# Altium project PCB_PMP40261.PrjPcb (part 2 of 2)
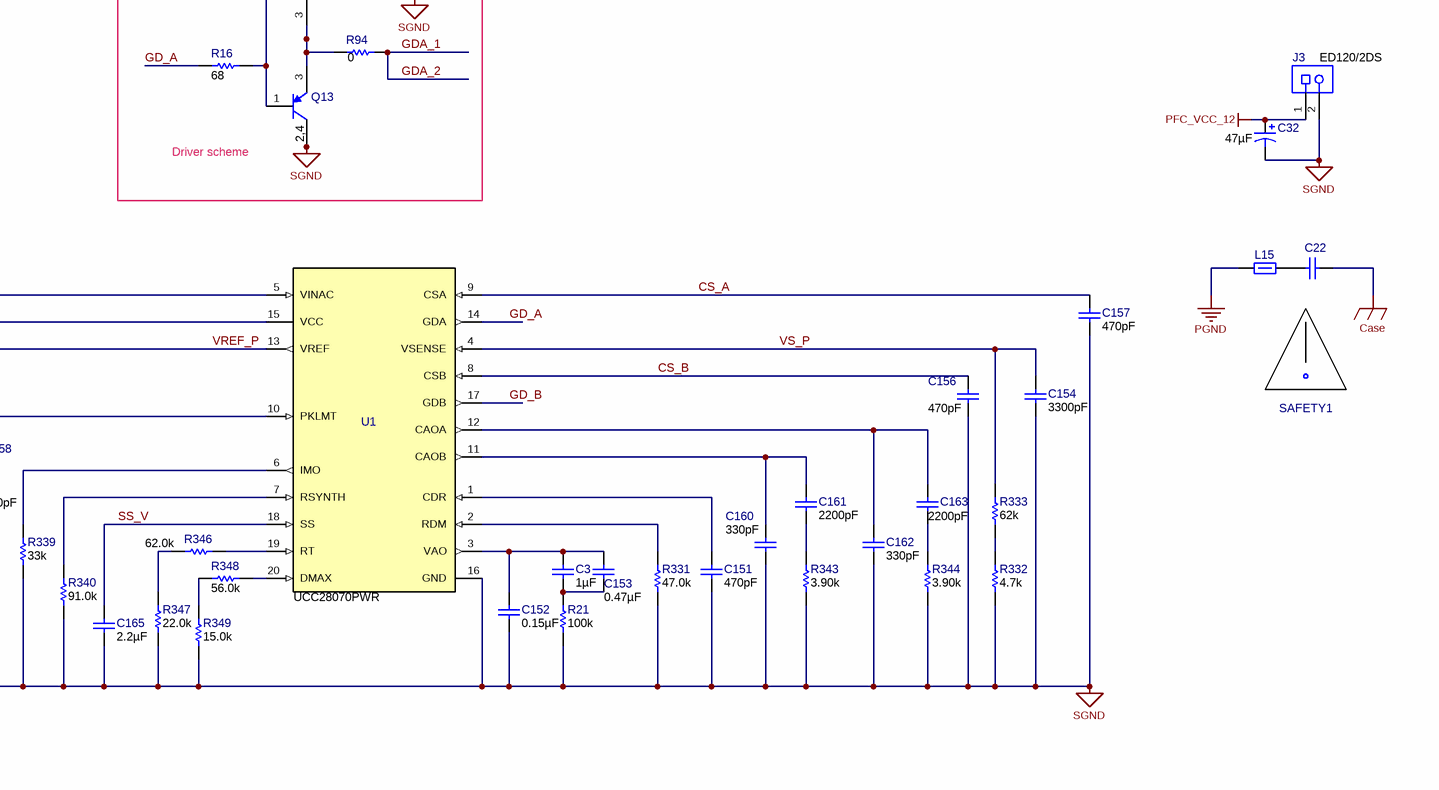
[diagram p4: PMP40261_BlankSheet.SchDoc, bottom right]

## Sheet PMP40261_BlankSheet.SchDoc (continued)

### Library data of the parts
C3 = UMK107AB7105KA-T: CAP, CERM, 1 µF, 50 V,+/- 10%, X7R, 0603; Manufacturer: Taiyo Yuden; Polarized: N; CompType: Capacitor; Value: 1uF; U/M: EA; Cap_F: 0.000001; Tolerance_%: 10; VDC_V: 50; Value2: 50V; TaMin_C: -55; TaMax_C: 125; SizeArea_mm2: 1.28; SizeAreaWB_mm2: 4.68; SizeX_mm: 1.6; SizeY_mm: 0.8; SizeZ_mm: 1; AEC Category: Q200; Green_Lifecycle: Active; Green_REACh: Passed
C11-C14 C41 = CMP-0078590-1: CAP, Film, 0.47 µF, X2 275 VAC, +/- 10%, TH; Manufacturer: Kemet; Cap_F: 470nF; SizeAreaWB_mm2: 210; VAC_X: 275; SizeArea_mm2: 153; AEC Qualified: N; AEC Category: Q200; Value: 0.47uF; TaMax_C: 110°C; SizeZ_mm: 14.6; TaMin_C: -40°C; SizeY_mm: 8.5; CompType: Capacitor; SizeX_mm: 18; Cap_Case: 18x8.5x14.5
C15 C16 = CMP-0009600-2: CAP, CERM, 1000 pF, 250 V, +/- 20%, E, Disc, 8x12mm; Manufacturer: MuRata; TaMin_C: -25°C; Polarized: N; SizeAreaWB_mm2: 100; Value1: Unknown; U/M: EA; Value: 1000pF; TaMax_C: 85°C; SizeZ_mm: 12; SizeX_mm: 8; Value2: 250V; SizeArea_mm2: 64; CompType: Capacitor; Cap_F: 1nF; AEC Category: Q200
C17 C18 = CMP-0009610-2: CAP, CERM, 2200 pF, 250 V, +/- 20%, E, Radial D8x5mm; Manufacturer: MuRata; TaMin_C: -25°C; Polarized: N; SizeAreaWB_mm2: 70; Value1: Unknown; U/M: EA; Value: 2200pF; TaMax_C: 85°C; SizeZ_mm: 11; SizeX_mm: 8; SizeY_mm: 5; Value2: 250V; SizeArea_mm2: 40; CompType: Capacitor; Cap_F: 2.2nF; AEC Category: Q200
C22 = CMP-0078745-1: CAP, CERM, 220 pF, X1 250 VAC/Y1 300 VAC, +/- 10%, B, 8x7mm; Manufacturer: MuRata; Cap_F: 220pF; SizeAreaWB_mm2: 158.76; VAC_X: 250V; VAC_Y: 300V; SizeArea_mm2: 112.36; AEC Qualified: N; AEC Category: Q200; Value: 220pF; TaMax_C: 125°C; SizeZ_mm: 11; TaMin_C: -40°C; SizeY_mm: 10.6; U/M: EA; AC_Safety: X1Y1; CompType: Capacitor
C27-C30 = CMP-0009975-3: CAP, AL, 150 uF, 450 V, +/- 20%, TH; Manufacturer: Rubycon; TaMax_C: 105°C; Value1: Unknown; SizeX_mm: 18; TaMin_C: -40°C; CompType: Capacitor; SizeZ_mm: 47; AEC Qualified: N; Value: 150uF; SizeArea_mm2: 324; AEC Category: Q200; SizeAreaWB_mm2: 400; U/M: EA; Polarized: Y; Cap_Case: 18x45mm; Cap_F: 150µF; IRMS_A: 1A
C31 = ECWF6223JL: CAP, Film, 0.022 µF, 630 V,+/- 5%, TH; Manufacturer: Panasonic; Polarized: N; CompType: Capacitor; Value: 0.022uF; U/M: EA; Cap_F: 0.000000022; Tolerance_%: 5; VDC_V: 630; Value2: 630V; TaMin_C: -40; TaMax_C: 105; Cap_Case: 12.5x6.2x10.5mm; AEC Category: Q200
C32 = EEU-FC1V470: CAP, AL, 47 µF, 35 V, +/- 20%, AEC-Q200 Grade 2, TH; Manufacturer: Panasonic; Polarized: Y; CompType: Capacitor; Value: 47uF; U/M: EA; Cap_F: 0.000047; Tolerance_%: 20; VDC_V: 35; Value2: 35V; IRMS_A: 0.29; TaMin_C: -55; TaMax_C: 105; Cap_Case: 6.3x11.2mm; SizeAreaWB_mm2: 68.89; SizeArea_mm2: 39.69; SizeX_mm: 6.3; SizeZ_mm: 12.2; AEC Category: Q200; AEC Grade: 2
C40 C43 C165 C181 = C2012X7R1H225K125AC: CAP, CERM, 2.2 µF, 50 V,+/- 10%, X7R, 0805; Manufacturer: TDK; Polarized: N; CompType: Capacitor; Value: 2.2uF; U/M: EA; Cap_F: 0.0000022; Tolerance_%: 10; ESR_ohm: 0.00366; Value1: 0.00366 ohm; VDC_V: 50; Value2: 50V; IRMS_A: 3.41207; TaMin_C: -55; TaMax_C: 125; Cap_Case: 0805; SizeArea_mm2: 2.5; SizeAreaWB_mm2: 6.75; SizeX_mm: 2; SizeY_mm: 1.25; SizeZ_mm: 1.45; AEC Category: Q200; Green_Lifecycle: Active; Green_REACh: Passed
C42 C44 C146 C159 C164 C178-C180 = GRM188R71H104KA93D: CAP, CERM, 0.1 µF, 50 V,+/- 10%, X7R, 0603; Manufacturer: MuRata; Polarized: N; CompType: Capacitor; Value: 0.1uF; U/M: EA; Cap_F: 0.0000001; Tolerance_%: 10; VDC_V: 50; Value2: 50V; TaMin_C: -55; TaMax_C: 125; SizeArea_mm2: 1.28; SizeAreaWB_mm2: 4.68; SizeX_mm: 1.6; SizeY_mm: 0.8; SizeZ_mm: 1; AEC Category: Q200; Green_Lifecycle: Active; Green_REACh: Passed
C80-C85 = CMP-0078744-1: CAP, CERM, 100 pF, 1000 V,+/- 10%, R, AEC-Q200 Grade 1, 6x5mm; Manufacturer: TDK; Cap_F: 100pF; SizeAreaWB_mm2: 56; SizeArea_mm2: 30; AEC Qualified: Y; AEC Category: Q200; Value: 100pF; TaMax_C: 125°C; SizeZ_mm: 10; AEC Grade: 1; Polarized: N; TaMin_C: -40°C; VDC_V: 1kV; SizeY_mm: 5; Value2: 1000V; U/M: EA; CompType: Capacitor; SizeX_mm: 6; Cap_Case: 6x5x10mm
C151 = 06031C471KAT2A: CAP, CERM, 470 pF, 100 V,+/- 10%, X7R, 0603; Manufacturer: AVX; Polarized: N; CompType: Capacitor; Value: 470pF; U/M: EA; Cap_F: 0.00000000047; Tolerance_%: 10; ESR_ohm: 0.397; Value1: 0.397 ohm; VDC_V: 100; Value2: 100V; TaMin_C: -55; TaMax_C: 125; SizeArea_mm2: 1.28; SizeAreaWB_mm2: 4.68; SizeX_mm: 1.6; SizeY_mm: 0.8; SizeZ_mm: 1; AEC Category: Q200; Green_Lifecycle: Not Set; Green_REACh: Incomplete
C152 = C1608X7R1E154K080AA: CAP, CERM, 0.15 µF, 25 V,+/- 10%, X7R, 0603; Manufacturer: TDK; Polarized: N; CompType: Capacitor; Value: 0.15uF; U/M: EA; Cap_F: 0.00000015; Tolerance_%: 10; VDC_V: 25; Value2: 25V; TaMin_C: -55; TaMax_C: 125; SizeArea_mm2: 1.28; SizeAreaWB_mm2: 4.68; SizeX_mm: 1.6; SizeY_mm: 0.8; SizeZ_mm: 1; AEC Category: Q200; Green_Lifecycle: Active; Green_REACh: Passed
C153 = C1608X7R1H474K080AC: CAP, CERM, 0.47 µF, 50 V,+/- 10%, X7R, 0603; Manufacturer: TDK; Polarized: N; CompType: Capacitor; Value: 0.47uF; U/M: EA; Cap_F: 0.00000047; Tolerance_%: 10; ESR_ohm: 0.010974; Value1: 0.010974 ohm; VDC_V: 50; Value2: 50V; IRMS_A: 1.57483; TaMin_C: -55; TaMax_C: 125; SizeArea_mm2: 1.28; SizeAreaWB_mm2: 4.68; SizeX_mm: 1.6; SizeY_mm: 0.8; SizeZ_mm: 1; AEC Category: Q200; Green_Lifecycle: Active; Green_REACh: Passed
C154 C155 = 06031C332JAT2A: CAP, CERM, 3300 pF, 100 V,+/- 5%, X7R, 0603; Manufacturer: AVX; Polarized: N; CompType: Capacitor; Value: 3300pF; U/M: EA; Cap_F: 0.0000000033; Tolerance_%: 5; ESR_ohm: 0.159; Value1: 0.159 ohm; VDC_V: 100; Value2: 100V; TaMin_C: -55; TaMax_C: 125; SizeArea_mm2: 1.28; SizeAreaWB_mm2: 4.68; SizeX_mm: 1.6; SizeY_mm: 0.8; SizeZ_mm: 1; AEC Category: Q200; Green_Lifecycle: Active; Green_REACh: Passed
C156 C157 = 06031C471JAT2A: CAP, CERM, 470 pF, 100 V,+/- 5%, X7R, 0603; Manufacturer: AVX; Polarized: N; CompType: Capacitor; Value: 470pF; U/M: EA; Cap_F: 0.00000000047; Tolerance_%: 5; ESR_ohm: 0.397; Value1: 0.397 ohm; VDC_V: 100; Value2: 100V; TaMin_C: -55; TaMax_C: 125; SizeArea_mm2: 1.28; SizeAreaWB_mm2: 4.68; SizeX_mm: 1.6; SizeY_mm: 0.8; SizeZ_mm: 1; AEC Category: Q200; Green_Lifecycle: Active; Green_REACh: Passed
C158 = 0603ZC101KAT2A: CAP, CERM, 100 pF, 10 V,+/- 10%, X7R, 0603; Manufacturer: AVX; Polarized: N; CompType: Capacitor; Value: 100pF; U/M: EA; Cap_F: 0.0000000001; Tolerance_%: 10; Value2: 10V; TaMin_C: -55; TaMax_C: 125; SizeArea_mm2: 1.28; SizeAreaWB_mm2: 4.68; SizeX_mm: 1.6; SizeY_mm: 0.8; SizeZ_mm: 1; AEC Category: Q200
C160 C162 = C0603C331K5RACTU: CAP, CERM, 330 pF, 50 V,+/- 10%, X7R, 0603; Manufacturer: Kemet; Polarized: N; CompType: Capacitor; Value: 330pF; U/M: EA; Cap_F: 0.00000000033; Tolerance_%: 10; VDC_V: 50; Value2: 50V; TaMin_C: -55; TaMax_C: 125; SizeArea_mm2: 1.28; SizeAreaWB_mm2: 4.68; SizeX_mm: 1.6; SizeY_mm: 0.8; SizeZ_mm: 1; AEC Category: Q200; Green_Lifecycle: Active; Green_REACh: Passed
C161 C163 = C0603C222K5RACTU: CAP, CERM, 2200 pF, 50 V,+/- 10%, X7R, 0603; Manufacturer: Kemet; Polarized: N; CompType: Capacitor; Value: 2200pF; U/M: EA; Cap_F: 0.0000000022; Tolerance_%: 10; VDC_V: 50; Value2: 50V; TaMin_C: -55; TaMax_C: 125; SizeArea_mm2: 1.28; SizeAreaWB_mm2: 4.68; SizeX_mm: 1.6; SizeY_mm: 0.8; SizeZ_mm: 1; AEC Category: Q200; Green_Lifecycle: Active; Green_REACh: Passed
D1 D2 = GBJ2510-F: Diode, Switching-Bridge, 1000 V, 25 A, TH; Manufacturer: Diodes Inc.; U/M: EA; Vf_V: 1.05; Value: 1000V; Value1: 25A; Value2: 1.05V; Io_A: 25; Vr_V: 1000; TJmax_C: 150; RJC_CperW: 0.6; SizeAreaWB_mm2: 211.2; SizeArea_mm2: 138; SizeX_mm: 30; SizeY_mm: 4.6; SizeZ_mm: 24; AEC Category: Q101; AEC Qualified: N
D3 D4 = CMP-0078592-2: Diode, Schottky, 650 V, 20 A, TH; Manufacturer: Rohm; Value2: 1.55V; Value1: 20A; SizeX_mm: 10.045; SizeY_mm: 4.445; SizeZ_mm: 20; AEC Qualified: N; Value: 650V; SizeArea_mm2: 44.650025; AEC Category: Q101; SizeAreaWB_mm2: 77.630025; Tjmax_C: 175°C; RJC_CperW: 3.2
D10-D13 = US1J-13-F: Diode, Ultrafast, 600 V, 1 A, SMA; Manufacturer: Diodes Inc.; U/M: EA; Vf_V: 1.7; Value: 600V; Value1: 1A; Value2: 1.7V; Io_A: 1; Vr_V: 600; TJmax_C: 150; SizeAreaWB_mm2: 37.3428; SizeArea_mm2: 16.3228; SizeX_mm: 5.59; SizeY_mm: 2.92; SizeZ_mm: 2.87; AEC Category: Q101; Green_Lifecycle: Active; Green_REACh: Passed
D14 D15 = RF071M2S: Diode, Ultrafast, 200 V, 1 A, SOD-123; Manufacturer: Rohm; U/M: EA; Vf_V: 0.85; Value: 200V; Value1: 1A; Value2: 0.85V; Io_A: 1; Vr_V: 200; TJmax_C: 150; SizeAreaWB_mm2: 13.095; SizeArea_mm2: 6.545; SizeX_mm: 3.85; SizeY_mm: 1.7; SizeZ_mm: 1.35; AEC Category: Q101; Green_Lifecycle: Not Set; Green_REACh: Incomplete
D16 D82 = 1N4148W-7-F: Diode, Ultrafast, 100 V, 0.3 A, SOD-123; Manufacturer: Diodes Inc.; U/M: EA; Vf_V: 1.25; Value: 100V; Value1: 0.15A; Value2: 1.25V; Io_A: 0.15; Vr_V: 100; TJmax_C: 150; SizeAreaWB_mm2: 13.095; SizeArea_mm2: 6.545; SizeX_mm: 3.85; SizeY_mm: 1.7; SizeZ_mm: 1.35; AEC Category: Q101; Green_Lifecycle: Active; Green_REACh: Passed
D20 D23 D25 D27 D65 = 1N4148W-7-F: Diode, Ultrafast, 100 V, 0.3A, SOD-123; Manufacturer: Diodes Inc.; U/M: EA; Vf_V: 1.25; Value: 100V; Value1: 0.15A; Value2: 1.25V; Io_A: 0.15; Vr_V: 100; TJmax_C: 150; SizeAreaWB_mm2: 13.095; SizeArea_mm2: 6.545; SizeX_mm: 3.85; SizeY_mm: 1.7; SizeZ_mm: 1.35; AEC Category: Q101; Green_Lifecycle: Active; Green_REACh: Passed
D21 D24 D26 D28 = BZT52B16-HE3-08: Diode, Zener, 16 V, 410 mW, AEC-Q101, SOD-123; Manufacturer: Vishay-Semiconductor; SymbolCreator: a0412235; U/M: EA; Power_W: 0.41; Vz_V: 16; Value1: 0.41W; RJA_CperW: 300; SizeAreaWB_mm2: 13.095; SizeArea_mm2: 6.545; SizeX_mm: 3.85; SizeY_mm: 1.7; SizeZ_mm: 1.35; AEC Category: Q101; AEC Qualified: Y
D50 = BAS16LT1G: Diode, Switching, 100 V, 0.2 A, SOT-23; Manufacturer: ON Semiconductor; U/M: EA; Vf_V: 1.25; Value: 100V; Value1: 0.2A; Value2: 1.25V; Io_A: 0.2; Vr_V: 100; TJmax_C: 150; SizeAreaWB_mm2: 14; SizeArea_mm2: 7.5; SizeX_mm: 2.5; SizeY_mm: 3; SizeZ_mm: 1.1; AEC Category: Q101; AEC Qualified: N; Green_Lifecycle: Active; Green_REACh: Passed
D51 = BAT54-7-F: Diode, Schottky, 30 V, 0.2 A, SOT-23; Manufacturer: Diodes Inc.; U/M: EA; Vf_V: 0.65; Value: 30V; Value1: 0.2A; Value2: 0.65V; Io_A: 0.2; Vr_V: 30; TJmax_C: 125; SizeAreaWB_mm2: 14; SizeArea_mm2: 7.5; SizeX_mm: 2.5; SizeY_mm: 3; SizeZ_mm: 1.1; AEC Category: Q101; Green_Lifecycle: Active; Green_REACh: Passed
F1 = CMP-0077109-1: Fuse, 12 A, 250 VAC, TH; Manufacturer: Shenzhen Deer Electronics Co., Ltd; Irating_A: 12A; SizeAreaWB_mm2: 216.6; VAC_V: 250V; SizeZ_mm: 5.8; SizeY_mm: 5.6; SizeX_mm: 26.5; SizeArea_mm2: 148.4
H2 = CMP-0078706-3: Heat Sink, 201x110x15mm; Manufacturer: Suzhou Baojieer
J1 = 1-1318301-2: Polarized Header, 7.92 mm, 2x1, Tin, TH; Manufacturer: TE Connectivity; SymbolCreator: a0412235; CompType: Connector; Pitch_mm: 7.92; Gender: Male; Shrouded: N; Row_Count: 1; Current_A: 7.5; Voltage_V: 250; Cert_UL: Y; Green_Lifecycle: Not Set; Green_REACh: Incomplete
J2 = ED120/3DS: Terminal Block, 5.08 mm, 3x1, Brass, TH; Manufacturer: On-Shore Technology; SymbolCreator: a0412235; Pitch_mm: 5.08; Gender: Female; Shrouded: N; Row_Count: 1; Current_A: 15; Voltage_V: 300; Cert_CULUS: Y; Green_Lifecycle: Not Set; Green_REACh: Incomplete
J3 = ED120/2DS: Terminal Block, 5.08 mm, 2x1, Brass, TH; Manufacturer: On-Shore Technology; SymbolCreator: a0412235; Pitch_mm: 5.08; Gender: Female; Shrouded: N; Row_Count: 1; Current_A: 15; Voltage_V: 300; Cert_CULUS: Y; Green_Lifecycle: Not Set; Green_REACh: Incomplete
K1 = CMP-0077099-1: Relay, SPDT (1 Form C), 16 A, 12 V, TH; Manufacturer: Omron Electronic Components; Coil Type: Non Latching; SizeAreaWB_mm2: 446.6; Contact Rating_A: 16A; Turn Off Voltage (Min)_VDC: 1.2V; SizeArea_mm2: 360.0; Turn On Voltage (Max)_VDC: 8.4V; Time Release (s): 5ms; SizeZ_mm: 15.7; Time Operate (s): 15ms; Coil Current_A: 33.3mA; Coil Voltage_VDC: 12V; SizeY_mm: 28.8; Coil Power_W: 400mW; SizeX_mm: 12.5; Coil Resistance_ohm: 360
L1-L4 = CMP-0078768-1: Inductor, Toroid, 130 µH, 0.018 ohm, TH; Manufacturer: Coilcraft; SizeAreaWB_mm2: 3136; SizeArea_mm2: 2916; AEC Qualified: N; AEC Category: Q200; Value: 130uH; SizeZ_mm: 28; SizeY_mm: 54; Value2: A; DCR_ohm: 0.018
L5 L6 = CMP-0077117-6: Coupled inductor, 2.5mH, TH; Manufacturer: Wurth Elektronik; SizeX_mm: 36.0; SizeZ_mm: 23.5; AEC Qualified: N; SizeArea_mm2: 1296.0; AEC Category: Q200; SizeAreaWB_mm2: 1444; Lp: 2500.0; Ns1toNp: 1.0
L7 = CMP-0078634-1: Coupled inductor, 4mH,  ohm, TH; Manufacturer: Wurth Elektronik; SizeAreaWB_mm2: 1444; SizeArea_mm2: 1296; AEC Qualified: N; AEC Category: Q200; SizeZ_mm: 23.5; SizeY_mm: 36
L8 = CMP-0077117-6: Shorted; PartNumber: 750343684; Manufacturer: Wurth Elektronik; SizeX_mm: 36.0; CompType: Coupled Inductor; SizeZ_mm: 23.5; AEC Qualified: N; SizeArea_mm2: 1296.0; AEC Category: Q200; SizeAreaWB_mm2: 1444; Lp: 2500.0; Ns1toNp: 1.0
L9-L12 = 28L0138-10R-10: Ferrite Bead, 75 ohm @ 100 MHz, 5 A, D3.51xL4.45mm; Manufacturer: Laird-Signal Integrity Products; Value: 75 ohm; Imax_A: 5; DCR_ohm: 0.01; Value1: 0.01 ohm; Value2: 5A; SizeAreaWB_mm2: 60.2243; SizeArea_mm2: 31.3443; SizeX_mm: 8.93; SizeY_mm: 3.51; SizeZ_mm: 3.76; ZTyp@100MHz_Ohm: 75; Green_Lifecycle: Not Set; Green_REACh: Incomplete
L15-L31 = 28L0138-10R-10: Ferrite Bead, 75 ohm @ 100 MHz, 5 A, D3.51xL4.45mm; Manufacturer: Laird-Signal Integrity Products; ValueDisplayed: 75 ohm; Value: 75 ohm; Imax_A: 5; DCR_ohm: 0.01; Value1: 0.01 ohm; Value2: 5A; SizeAreaWB_mm2: 60.2243; SizeArea_mm2: 31.3443; SizeX_mm: 8.93; SizeY_mm: 3.51; SizeZ_mm: 3.76; ZTyp@100MHz_Ohm: 75; Green_Lifecycle: Not Set; Green_REACh: Incomplete
L40 = CMP-0078767-1: Inductor, Toroid, 220 µH, 0.018 ohm, TH; Manufacturer: Coilcraft; SizeAreaWB_mm2: 1560.25; SizeArea_mm2: 1406.25; AEC Qualified: N; AEC Category: Q200; Value: 220uH; SizeZ_mm: 29; SizeY_mm: 37.5; Value2: A; DCR_ohm: 0.018
NT1-NT3 = Net-Tie: Single point connection between nets.; SymbolCreator: codlsc
Q1-Q4 = CMP-0078591-1: MOSFET, N-CH, 600 V, 35 A, TO-247; Manufacturer: Infineon Technologies; Alternate Manufacturer: None; ChType: N; QgTyp_nC: 68; SizeAreaWB_mm2: 600.8691; SizeArea_mm2: 501.9591; IdsMax_A: 35A; VdsMax_V: 600V; Vgs_V: 20V; AEC Category: Q101; Value: 600V; SizeZ_mm: 5.21; SizeY_mm: 31.54; Value2: 68 nC; U/M: EA; Value1: ? ohm; SizeX_mm: 15.915
Q5 = 2N7002K-T1-E3: MOSFET, N-CH, 60 V, 0.3 A, SOT-23; Manufacturer: Vishay-Siliconix; Alternate Manufacturer: None; SymbolCreator: a0411947; U/M: EA; ChType: N; Value: 60V; VdsMax_V: 60; Value1: 4 ohm; Rdson45_ohm: 4; Value2: 0.4 nC; QgTyp_nC: 0.4; Vgs_V: 20; IdsMax_A: 0.3; SizeAreaWB_mm2: 14; SizeArea_mm2: 7.5; SizeX_mm: 2.5; SizeY_mm: 3; SizeZ_mm: 1.1; AEC Category: Q101; Green_Lifecycle: Active; Green_REACh: Passed
Q6 = CMP-0077159-1: MOSFET, P-CH, -30 V, -4 A, SOT-23; Manufacturer: AOS; Alternate Manufacturer: None; ChType: P; QgTyp_nC: 14.0; SizeArea_mm2: 7.5; IdsMax_A: -4A; AEC Qualified: N; VdsMax_V: -30V; Rdson45_ohm: 0.06; Vgs_V: -12V; AEC Category: Q101; Value: -30V; SizeZ_mm: 1.1; SizeY_mm: 3.0; Value2: 14 nC; U/M: EA; Value1: .06 ohm; SizeX_mm: 2.5
Q7 = MMBT4401-7-F, Diodes Inc.: Transistor, NPN, 40 V, 0.15 A, SOT-23; CompType: BJT; PNP: 0; NPN: 1; Vceo_V: 40; Vcesat1_V: 0.4; Value: 40 V; IcRated_A: 0.15; Value1: 0.15 A; HfeMax: 300; TaMin_C: -55; TaMax_C: 150; SizeAreaWB_mm2: 14; SizeArea_mm2: 7.5; SizeX_mm: 2.5; SizeY_mm: 3; SizeZ_mm: 1.1; U/M: EA; AEC Category: Q101; Green_Lifecycle: Active; Green_REACh: Passed
Q10 Q12 = PBSS4250X,115, Nexperia: Transistor, NPN, 50 V, 2 A, SOT-89; SymbolCreator: a0412235; PNP: 0; NPN: 1; Vceo_V: 50; Vcesat1_V: 0.25; Value: 50 V; IcRated_A: 2; Value1: 2 A; TaMin_C: -65; TaMax_C: 150; SizeAreaWB_mm2: 28.05; SizeArea_mm2: 18.45; SizeX_mm: 4.1; SizeY_mm: 4.5; SizeZ_mm: 1.5; CompType: BJT; U/M: EA; AEC Category: Q101; AEC Qualified: N
Q11 Q13 = PBSS5250X,115, Nexperia: Transistor, PNP, 50 V, 2 A, SOT-89; CompType: BJT; PNP: 1; NPN: 0; Vceo_V: 50; Vcesat1_V: 0.09; Value: 50 V; IcRated_A: 2; Value1: 2 A; TaMin_C: -65; TaMax_C: 150; SizeAreaWB_mm2: 28.05; SizeArea_mm2: 18.45; SizeX_mm: 4.1; SizeY_mm: 4.5; SizeZ_mm: 1.5; U/M: EA; AEC Category: Q101; AEC Qualified: N
R1-R6 R32 R33 R350 R351 R381 R382 = CRCW12061M00FKEA: RES, 1.00 M, 1%, 0.25 W, 1206; Manufacturer: Vishay-Dale; CompType: Resistor; Value: 1.00Meg; Res_ohm: 1000000; Value_Code: 1M00; Tolerance_%: 1; Power_W: 0.25; Value2: 0.25W; VDC_V: 200; TempCo: 100 ppm/C; SizeArea_mm2: 5.12; SizeX_mm: 3.2; SizeY_mm: 1.6; SizeZ_mm: 1.35; EIA_Code: E96; U/M: EA; AEC Category: Q200; Green_Lifecycle: Active; Green_REACh: Passed
R10 R13 = RC1206FR-074R7L: RES, 4.70, 1%, 0.25 W, 1206; Manufacturer: Yageo America; CompType: Resistor; Value: 4.70; Res_ohm: 4.7; Value_Code: 4R70; Tolerance_%: 1; Power_W: 0.25; Value2: 0.25W; VDC_V: 200; TempCo: 200 ppm/C; SizeArea_mm2: 5.12; SizeX_mm: 3.2; SizeY_mm: 1.6; SizeZ_mm: 1.35; U/M: EA; AEC Category: Q200
R11 R14 R16 R43 R46 R49 = CMP-0018717-3: RES, 68, 5%, 0.25 W, AEC-Q200 Grade 0, 1206; Manufacturer: Vishay-Dale; Power_W: 250mW; TempCo: 200 ppm/C; Value_Code: 68R0; Value: 68; EIA_Code: E24; SizeX_mm: 3.2; SizeY_mm: 1.6; SizeZ_mm: 1.35; Value2: 0.25W; SizeArea_mm2: 5.12; AEC Qualified: Y; VDC_V: 200V; AEC Category: Q200; AEC Grade: 0
R15 R25 R44 R47 R50 R388 = CRCW080510K0JNEA: RES, 10 k, 5%, 0.125 W, 0805; Manufacturer: Vishay-Dale; CompType: Resistor; Value: 10k; Res_ohm: 10000; Value_Code: 10k0; Tolerance_%: 5; Power_W: 0.125; Value2: 0.125W; VDC_V: 150; TempCo: 200 ppm/C; SizeArea_mm2: 2.5; SizeX_mm: 2; SizeY_mm: 1.25; SizeZ_mm: 1.45; EIA_Code: E24; U/M: EA; AEC Category: Q200; Green_Lifecycle: Active; Green_REACh: Passed
R21 R54 = CRCW0603100KFKEA: RES, 100 k, 1%, 0.1 W, 0603; Manufacturer: Vishay-Dale; CompType: Resistor; Value: 100k; Res_ohm: 100000; Tolerance_%: 1; Power_W: 0.1; Value2: 0.1W; VDC_V: 75; TempCo: 100 ppm/C; SizeArea_mm2: 1.28; SizeX_mm: 1.6; SizeY_mm: 0.8; EIA_Code: E96; U/M: EA; AEC Category: Q200; Green_Lifecycle: Active; Green_REACh: Passed
R30 R31 R334 R335 R379 R380 = CRCW12063M30JNEA: RES, 3.3 M, 1%, 0.25 W, 1206; Manufacturer: Vishay-Dale; CompType: Resistor; Value: 3.3Meg; Res_ohm: 3300000; Value_Code: 3M30; Tolerance_%: 5; Power_W: 0.25; Value2: 0.25W; VDC_V: 200; TempCo: 200 ppm/C; SizeArea_mm2: 5.12; SizeX_mm: 3.2; SizeY_mm: 1.6; SizeZ_mm: 1.35; EIA_Code: E24; U/M: EA; AEC Category: Q200
R41 R45 = CMP-0017851-2: RES, 10.0, 1%, 0.25 W, 1206; Manufacturer: Yageo America; Power_W: 250mW; TempCo: 200 ppm/C; Value_Code: 10R0; U/M: EA; Value: 10.0; EIA_Code: E96; Res_ohm: 10; SizeX_mm: 3.2; SizeY_mm: 1.6; SizeZ_mm: 1.35; Value2: 0.25W; SizeArea_mm2: 5.12; VDC_V: 200V; AEC Category: Q200
R42 R48 = RC1206FR-0733RL: RES, 33.0, 1%, 0.25 W, 1206; Manufacturer: Yageo America; CompType: Resistor; Value: 33.0; Res_ohm: 33; Value_Code: 33R0; Tolerance_%: 1; Power_W: 0.25; Value2: 0.25W; VDC_V: 200; TempCo: 100 ppm/C; SizeArea_mm2: 5.12; SizeX_mm: 3.2; SizeY_mm: 1.6; SizeZ_mm: 1.35; U/M: EA; AEC Category: Q200; Green_Lifecycle: Active; Green_REACh: Passed
R51 = RC0603FR-075K1L: RES, 5.10 k, 1%, 0.1 W, 0603; Manufacturer: Yageo America; CompType: Resistor; Value: 5.10k; Res_ohm: 5100; Value_Code: 5k10; Tolerance_%: 1; Power_W: 0.1; Value2: 0.1W; VDC_V: 150; TempCo: 200 ppm/C; SizeArea_mm2: 1.28; SizeX_mm: 1.6; SizeY_mm: 0.8; U/M: EA; AEC Category: Q200; Green_Lifecycle: Active; Green_REACh: Passed
R52 R53 R55 = RC0603FR-0712KL: RES, 12.0 k, 1%, 0.1 W, 0603; Manufacturer: Yageo America; CompType: Resistor; Value: 12.0k; Res_ohm: 12000; Value_Code: 12k0; Tolerance_%: 1; Power_W: 0.1; Value2: 0.1W; VDC_V: 150; TempCo: 200 ppm/C; SizeArea_mm2: 1.28; SizeX_mm: 1.6; SizeY_mm: 0.8; U/M: EA; AEC Category: Q200; Green_Lifecycle: Active; Green_REACh: Passed
R60-R91 = ERJ-8ENF39R0V: RES, 39.0, 1%, 0.25 W, AEC-Q200 Grade 0, 1206; Manufacturer: Panasonic; CompType: Resistor; Value: 39.0; Res_ohm: 39; Value_Code: 39R0; Tolerance_%: 1; Power_W: 0.25; Value2: 0.25W; TempCo: 100 ppm/C; SizeArea_mm2: 5.12; SizeX_mm: 3.2; SizeY_mm: 1.6; SizeZ_mm: 1.35; U/M: EA; AEC Category: Q200; AEC Qualified: Y; AEC Grade: 0
R92-R97 = 5108: RES, 0, 1%, 0.5 W, 1206; Manufacturer: Keystone; CompType: Resistor; Value: 0; Tolerance_%: 1; Power_W: 0.5; Value2: 0.5W; TempCo: ppm/C; SizeArea_mm2: 5.185; SizeX_mm: 3.05; SizeY_mm: 1.7; SizeZ_mm: 0.84; U/M: EA; AEC Category: Q200; AEC Qualified: N
R315 = RC1206FR-072R2L: RES, 2.20, 1%, 0.25 W, 1206; Manufacturer: Yageo America; CompType: Resistor; Value: 2.20; Res_ohm: 2.2; Value_Code: 2R20; Tolerance_%: 1; Power_W: 0.25; Value2: 0.25W; VDC_V: 200; TempCo: 200 ppm/C; SizeArea_mm2: 5.12; SizeX_mm: 3.2; SizeY_mm: 1.6; SizeZ_mm: 1.35; U/M: EA; AEC Category: Q200
R316 = RC1206FR-0710RL: RES, 10.0, 1%, 0.25 W, 1206; Manufacturer: Yageo America; CompType: Resistor; Value: 10.0; Res_ohm: 10; Value_Code: 10R0; Tolerance_%: 1; Power_W: 0.25; Value2: 0.25W; VDC_V: 200; TempCo: 200 ppm/C; SizeArea_mm2: 5.12; SizeX_mm: 3.2; SizeY_mm: 1.6; SizeZ_mm: 1.35; EIA_Code: E96; U/M: EA; AEC Category: Q200; Green_Lifecycle: Active; Green_REACh: Passed
R323 R327 = CRCW12061K50FKEA: RES, 1.50 k, 1%, 0.25 W, 1206; Manufacturer: Vishay-Dale; CompType: Resistor; Value: 1.50k; Res_ohm: 1500; Value_Code: 1k50; Tolerance_%: 1; Power_W: 0.25; Value2: 0.25W; VDC_V: 200; TempCo: 100 ppm/C; SizeArea_mm2: 5.12; SizeX_mm: 3.2; SizeY_mm: 1.6; SizeZ_mm: 1.35; EIA_Code: E96; U/M: EA; AEC Category: Q200; Green_Lifecycle: Active; Green_REACh: Passed
R324 R328 = RC0603FR-073K3L: RES, 3.30 k, 1%, 0.1 W, 0603; Manufacturer: Yageo America; CompType: Resistor; Value: 3.30k; Res_ohm: 3300; Value_Code: 3k30; Tolerance_%: 1; Power_W: 0.1; Value2: 0.1W; VDC_V: 150; TempCo: 200 ppm/C; SizeArea_mm2: 1.28; SizeX_mm: 1.6; SizeY_mm: 0.8; U/M: EA; AEC Category: Q200; Green_Lifecycle: Active; Green_REACh: Passed
R325 R329 = RC1206FR-0743RL: RES, 43.0, 1%, 0.25 W, 1206; Manufacturer: Yageo America; CompType: Resistor; Value: 43.0; Res_ohm: 43; Value_Code: 43R0; Tolerance_%: 1; Power_W: 0.25; Value2: 0.25W; VDC_V: 200; TempCo: 100 ppm/C; SizeArea_mm2: 5.12; SizeX_mm: 3.2; SizeY_mm: 1.6; SizeZ_mm: 1.35; U/M: EA; AEC Category: Q200
R326 R330 = CRCW08051K00JNEA: RES, 1.0 k, 5%, 0.125 W, 0805; Manufacturer: Vishay-Dale; CompType: Resistor; Value: 1.0k; Res_ohm: 1000; Value_Code: 1k00; Tolerance_%: 5; Power_W: 0.125; Value2: 0.125W; VDC_V: 150; TempCo: 200 ppm/C; SizeArea_mm2: 2.5; SizeX_mm: 2; SizeY_mm: 1.25; SizeZ_mm: 1.45; EIA_Code: E24; U/M: EA; AEC Category: Q200; Green_Lifecycle: Active; Green_REACh: Passed
R331 = CRCW060347K0FKEA: RES, 47.0 k, 1%, 0.1 W, AEC-Q200 Grade 0, 0603; Manufacturer: Vishay-Dale; CompType: Resistor; Value: 47.0k; Res_ohm: 47000; Value_Code: 47k0; Tolerance_%: 1; Power_W: 0.1; Value2: 0.1W; VDC_V: 75; TempCo: 100 ppm/C; SizeArea_mm2: 1.28; SizeX_mm: 1.6; SizeY_mm: 0.8; U/M: EA; AEC Category: Q200; AEC Qualified: Y; AEC Grade: 0
R332 R337 = CRCW08054K70JNEA: RES, 4.7 k, 1%, 0.125 W, 0805; Manufacturer: Vishay-Dale; CompType: Resistor; Value: 4.7k; Res_ohm: 4700; Value_Code: 4k70; Tolerance_%: 5; Power_W: 0.125; Value2: 0.125W; VDC_V: 150; TempCo: 200 ppm/C; SizeArea_mm2: 2.5; SizeX_mm: 2; SizeY_mm: 1.25; SizeZ_mm: 1.45; EIA_Code: E24; U/M: EA; AEC Category: Q200; Green_Lifecycle: Active; Green_REACh: Passed
R333 R338 = ERJ-6GEYJ623V: RES, 62 k, 1%, 0.125 W, 0805; Manufacturer: Panasonic; CompType: Resistor; Value: 62k; Res_ohm: 62000; Value_Code: 62k0; Tolerance_%: 5; Power_W: 0.125; Value2: 0.125W; VDC_V: 150; TempCo: 200 ppm/C; SizeArea_mm2: 2.5; SizeX_mm: 2; SizeY_mm: 1.25; SizeZ_mm: 1.45; EIA_Code: E24; U/M: EA; AEC Category: Q200
R339 = RC0603FR-0724KL: RES, 24.0 k, 1%, 0.1 W, 0603; Manufacturer: Yageo America; CompType: Resistor; Value: 24.0k; Res_ohm: 24000; Value_Code: 24k0; Tolerance_%: 1; Power_W: 0.1; Value2: 0.1W; VDC_V: 150; TempCo: 200 ppm/C; SizeArea_mm2: 1.28; SizeX_mm: 1.6; SizeY_mm: 0.8; U/M: EA; AEC Category: Q200; Green_Lifecycle: Active; Green_REACh: Passed
R340 = RC0603FR-0791KL: RES, 91.0 k, 1%, 0.1 W, 0603; Manufacturer: Yageo America; CompType: Resistor; Value: 91.0k; Res_ohm: 91000; Value_Code: 91k0; Tolerance_%: 1; Power_W: 0.1; Value2: 0.1W; VDC_V: 150; TempCo: 200 ppm/C; SizeArea_mm2: 1.28; SizeX_mm: 1.6; SizeY_mm: 0.8; U/M: EA; AEC Category: Q200
R341 = CRCW060313K0FKEA: RES, 13.0 k, 1%, 0.1 W, 0603; Manufacturer: Vishay-Dale; CompType: Resistor; Value: 13.0k; Res_ohm: 13000; Value_Code: 13k0; Tolerance_%: 1; Power_W: 0.1; Value2: 0.1W; VDC_V: 75; TempCo: 100 ppm/C; SizeArea_mm2: 1.28; SizeX_mm: 1.6; SizeY_mm: 0.8; EIA_Code: E96; U/M: EA; AEC Category: Q200; Green_Lifecycle: Active; Green_REACh: Passed
R342 = CRCW060310K0FKEA: RES, 10.0 k, 1%, 0.1 W, 0603; Manufacturer: Vishay-Dale; CompType: Resistor; Value: 10.0k; Res_ohm: 10000; Value_Code: 10k0; Tolerance_%: 1; Power_W: 0.1; Value2: 0.1W; VDC_V: 75; TempCo: 100 ppm/C; SizeArea_mm2: 1.28; SizeX_mm: 1.6; SizeY_mm: 0.8; EIA_Code: E96; U/M: EA; AEC Category: Q200; Green_Lifecycle: Active; Green_REACh: Passed
R343 R344 = CRCW06033K90FKEA: RES, 3.90 k, 1%, 0.1 W, 0603; Manufacturer: Vishay-Dale; CompType: Resistor; Value: 3.90k; Res_ohm: 3900; Value_Code: 3k90; Tolerance_%: 1; Power_W: 0.1; Value2: 0.1W; TempCo: 100 ppm/C; SizeArea_mm2: 1.28; SizeX_mm: 1.6; SizeY_mm: 0.8; U/M: EA; AEC Category: Q200
R345 = CRCW08054R70JNEA: RES, 4.7, 5%, 0.125 W, 0805; Manufacturer: Vishay-Dale; CompType: Resistor; Value: 4.7; Value_Code: 4R70; Tolerance_%: 5; Power_W: 0.125; Value2: 0.125W; VDC_V: 150; TempCo: 200 ppm/C; SizeArea_mm2: 2.5; SizeX_mm: 2; SizeY_mm: 1.25; SizeZ_mm: 1.45; EIA_Code: E24; U/M: EA; AEC Category: Q200; Green_Lifecycle: Active; Green_REACh: Passed
R346 = RC0603FR-0762KL: RES, 62.0 k, 1%, 0.1 W, 0603; Manufacturer: Yageo America; CompType: Resistor; Value: 62.0k; Res_ohm: 62000; Value_Code: 62k0; Tolerance_%: 1; Power_W: 0.1; Value2: 0.1W; VDC_V: 150; TempCo: 200 ppm/C; SizeArea_mm2: 1.28; SizeX_mm: 1.6; SizeY_mm: 0.8; U/M: EA; AEC Category: Q200; Green_Lifecycle: Active; Green_REACh: Passed
R347 = ERJ-3EKF2202V: RES, 22.0 k, 1%, 0.1 W, AEC-Q200 Grade 0, 0603; Manufacturer: Panasonic; CompType: Resistor; Value: 22.0k; Res_ohm: 22000; Value_Code: 22k0; Tolerance_%: 1; Power_W: 0.1; Value2: 0.1W; VDC_V: 50; TempCo: 100 ppm/C; SizeArea_mm2: 1.28; SizeX_mm: 1.6; SizeY_mm: 0.8; U/M: EA; AEC Category: Q200; AEC Qualified: Y; AEC Grade: 0; Green_Lifecycle: Active; Green_REACh: Passed
R348 = RG1608P-563-B-T5: RES, 56.0 k, 0.1%, 0.1 W, 0603; Manufacturer: Susumu Co Ltd; CompType: Resistor; Value: 56.0k; Res_ohm: 56000; Value_Code: 56k0; Tolerance_%: 0.1; Value2: 0.1W; VDC_V: 75; TempCo: 25 ppm/C; SizeArea_mm2: 1.28; SizeX_mm: 1.6; SizeY_mm: 0.8; SizeZ_mm: 1; U/M: EA; AEC Category: Q200
R349 = CRCW060315K0FKEA: RES, 15.0 k, 1%, 0.1 W, 0603; Manufacturer: Vishay-Dale; CompType: Resistor; Value: 15.0k; Res_ohm: 15000; Value_Code: 15k0; Tolerance_%: 1; Power_W: 0.1; Value2: 0.1W; VDC_V: 75; TempCo: 100 ppm/C; SizeArea_mm2: 1.28; SizeX_mm: 1.6; SizeY_mm: 0.8; EIA_Code: E96; U/M: EA; AEC Category: Q200; Green_Lifecycle: Active; Green_REACh: Passed
R377 R385-R387 = ERJ-6GEYJ332V: RES, 3.3 k, 5%, 0.125 W, 0805; Manufacturer: Panasonic; CompType: Resistor; Value: 3.3k; Res_ohm: 3300; Value_Code: 3k30; Tolerance_%: 5; Power_W: 0.125; Value2: 0.125W; VDC_V: 150; TempCo: 200 ppm/C; SizeArea_mm2: 2.5; SizeX_mm: 2; SizeY_mm: 1.25; SizeZ_mm: 1.45; EIA_Code: E24; U/M: EA; AEC Category: Q200
R378 = CRCW080512K0JNEA: RES, 12 k, 5%, 0.125 W, 0805; Manufacturer: Vishay-Dale; CompType: Resistor; Value: 12k; Res_ohm: 12000; Value_Code: 12k0; Tolerance_%: 5; Power_W: 0.125; Value2: 0.125W; VDC_V: 150; TempCo: 200 ppm/C; SizeArea_mm2: 2.5; SizeX_mm: 2; SizeY_mm: 1.25; SizeZ_mm: 1.45; EIA_Code: E24; U/M: EA; AEC Category: Q200
R383 = CRCW0805360KJNEA: RES, 360 k, 5%, 0.125 W, 0805; Manufacturer: Vishay-Dale; CompType: Resistor; Value: 360k; Res_ohm: 360000; Tolerance_%: 5; Power_W: 0.125; Value2: 0.125W; VDC_V: 150; TempCo: 200 ppm/C; SizeArea_mm2: 2.5; SizeX_mm: 2; SizeY_mm: 1.25; SizeZ_mm: 1.45; EIA_Code: E24; U/M: EA; AEC Category: Q200
R384 = RC1206FR-0751KL: RES, 51.0 k, 1%, 0.25 W, 1206; Manufacturer: Yageo America; CompType: Resistor; Value: 51.0k; Res_ohm: 51000; Value_Code: 51k0; Tolerance_%: 1; Power_W: 0.25; Value2: 0.25W; VDC_V: 200; TempCo: 100 ppm/C; SizeArea_mm2: 5.12; SizeX_mm: 3.2; SizeY_mm: 1.6; SizeZ_mm: 1.35; U/M: EA; AEC Category: Q200
RT1 RT2 = CMP-0078760-1: Thermistor NTC, 5 ohm, 20%, D20xT6mm; Manufacturer: TKS; SizeAreaWB_mm2: 176; SizeArea_mm2: 120; Value: 5; TaMax_C: 200°C; SizeZ_mm: 24.5; TaMin_C: -40°C; Power_W: 4.9W; SizeY_mm: 20; U/M: EA; SizeX_mm: 6
RT3 = NCP18XH103J03RB: Thermistor NTC, 10k ohm, 5%, 0603; Manufacturer: MuRata; Tolerance_%: 5; Power_W: 0.1; TaMin_C: -40; TaMax_C: 125; SizeAreaWB_mm2: 4.68; SizeArea_mm2: 1.28; SizeX_mm: 1.6; SizeY_mm: 0.8; SizeZ_mm: 1; U/M: EA
RV1 = CMP-0078703-1: SIOV Metal Oxide Varistor 420V, 4.5kA, TH; Manufacturer: TDK; SizeAreaWB_mm2: 141.75; SizeArea_mm2: 94.55; SizeZ_mm: 19; SizeY_mm: 6.1; SizeX_mm: 15.5
T1 T2 = CS4200V-01L: Transformer , Current sense, 80 mH, TH; Manufacturer: Coilcraft; SymbolCreator: a0799628; Value: 80mH; Lp: 80000; Ind_H: 0.08; Green_Lifecycle: Not Set; Green_REACh: Incomplete
U1 = UCC28070PWR: Two-Phase Interleaved CCM PFC Controller, PW0020A (TSSOP-20); Manufacturer: Texas Instruments; SymbolCreator: a0411947; SizeArea_mm2: 43.56; SizeAreaWB_mm2: 73.96; SizeX_mm: 6.6; SizeZ_mm: 1.2; CompType: IC; U/M: EA
U4 = TL431AIDBZR: Adjustable Precision Shunt Regulator, 34 ppm / degC, 100 mA, -40 to 85 degC, 3-pin SOT-23 (DBZ), Green (RoHS & no Sb/Br); Manufacturer: Texas Instruments; Alternate PartNumber: Equivalent; Initial Accuracy @ 25/deg C(%): 1; Iout/Iz(Max)(mA): 100; Min Iz for Regulation(uA): 600; Rating: Catalog; SubFamily: Shunt Voltage Reference; Temp Coeff(Max)(ppm/ degree C): 92; Temp Coeff(Typ)(ppm/ degree C): 34; VO Adj(Max)(V): 36; VO Adj(Min)(V): 2.495
U5 = LM293AD: Dual Comparator, D0008A; Manufacturer: Texas Instruments; CompType: OpAmp IC

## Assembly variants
001: not fitted C22 C80 C81 C82 C83 C84 C85 D20 D23 D24 D25 D27 D28 L8 L15 Q2 Q4 R14 R42 R43 R44 R46 R48 R49 R50 R60 R61 R62 R63 R64 R65 R66 R67 R68 R69 R70 R71 R72 R73 R74 R75 R76 R77 R78 R79 R80 R81 R82 R83 R84 R85 R86 R87 R88 R89 R90 R91 R96 R97 RV1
